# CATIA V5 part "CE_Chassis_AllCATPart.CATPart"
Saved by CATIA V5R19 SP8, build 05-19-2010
Part number: CE1_Chassis_AllCATPart
Bounding box of the stored display mesh (mm): x -239.06 to 490.902, y -240.361 to 577.812, z 217.448 to 1467.764
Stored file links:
  D:\Documents\1_Travail\1 - ac-limoges.fr\ac-limoges.fr\Emmanuel Maynard - STI2D_Turgot\2 -2I2D\1_SEQUENCE_ Tapis_de_course\3- Spécificités\Spé_ITEC\3-Pente\Tapis_TC520B_Pente\CE_Chassis_AllCATPart.CATPart
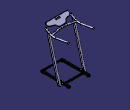
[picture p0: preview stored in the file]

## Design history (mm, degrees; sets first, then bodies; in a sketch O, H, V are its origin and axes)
AxisSystem1: origin (125.9211, -227.6434, 238.4484), X (1, 0, 0), Y (0, 1, 0), Z (0, 0, 1)
Set1 "S/S Cadre.1\\Cadre Chasis (1).1\\Références externes"
  DatumSurface1
Set2 "S/S Cadre.1\\Cadre Chasis (1).1\\Set géométrique.1"
  Sketch1 "Esquisse.38", origin (125.9211, -238.3614, 255.4484), H (0, 1, 0), V (0, 0, 1), geometry linked from another document
Body1 (main body)
  Point1: type OnCurve, Support edge [face of Solid2 | face of Solid2], Ratio 0.5
Body2 "S/S Cadre.1\\Cadre Chasis (1).1"
  Solid1: solid without history
  Body3 "S/S Cadre.1\\Cadre Chasis (1).1\\Traverses"
    Solid2 "Solide.1": solid without history
  Add1 "S/S Cadre.1\\Cadre Chasis (1).1\\Traverses": tool Body3
  Body4 "S/S Cadre.1\\Cadre Chasis (1).1\\renfort d'angle"
    Solid3 "Solide.1": solid without history
  Add2 "S/S Cadre.1\\Cadre Chasis (1).1\\renfort d'angle": tool Body4
  Body5 "S/S Cadre.1\\Cadre Chasis (1).1\\Ecrou_soudé H -M8"
    Solid4 "Solide.1": solid without history
  Add3 "S/S Cadre.1\\Cadre Chasis (1).1\\Ecrou_soudé H -M8": tool Body5
  Body6 "S/S Cadre.1\\Cadre Chasis (1).1\\Ecrou soudé H-M10"
    Solid5 "Solide.1": solid without history
  Add4 "S/S Cadre.1\\Cadre Chasis (1).1\\Ecrou soudé H-M10": tool Body6
  Body7 "S/S Cadre.1\\Cadre Chasis (1).1\\Chappe Vérin"
    Solid6 "Solide.1": solid without history
  Add5 "S/S Cadre.1\\Cadre Chasis (1).1\\Chappe Vérin": tool Body7
Body8 "S/S Cadre.1\\Patin (54).2"
  Solid7 "Solide.1": solid without history
  Body9 "S/S Cadre.1\\Patin (54).2\\Vis"
    Solid8 "Solide.1": solid without history
  Add6 "S/S Cadre.1\\Patin (54).2\\Vis": tool Body9
Body10 "S/S Cadre.1\\Patin (54).1"
  Solid9 "Solide.1": solid without history
  Body11 "S/S Cadre.1\\Patin (54).1\\Vis"
    Solid10 "Solide.1": solid without history
  Add7 "S/S Cadre.1\\Patin (54).1\\Vis": tool Body11
Body12 "S/S Cadre.1\\Patin (54).3"
  Solid11 "Solide.1": solid without history
  Body13 "S/S Cadre.1\\Patin (54).3\\Vis"
    Solid12 "Solide.1": solid without history
  Add8 "S/S Cadre.1\\Patin (54).3\\Vis": tool Body13
Body14 "S/S Cadre.1\\Patin (54).4"
  Solid13 "Solide.1": solid without history
  Body15 "S/S Cadre.1\\Patin (54).4\\Vis"
    Solid14 "Solide.1": solid without history
  Add9 "S/S Cadre.1\\Patin (54).4\\Vis": tool Body15
Body16 "S/S Cadre.1\\Part1.9\\Corps principal"
  Solid15 "Solide.1": solid without history
Body17 "S/S Cadre.1\\Part1.2\\Corps principal"
  Solid16 "Solide.1": solid without history
Body18 "S/S Cadre.1\\Vis Epaulée Tetebombee a six pan creux M10x23-9.1\\screw_gb_t_70_2_m10x25"
  Solid17 "Solide.1": solid without history
Body19 "S/S Cadre.1\\Rondelle plastique M12.1\\Corps principal"
  Solid18 "Solide.1": solid without history
Body20 "S/S Cadre.1\\Vis Epaulée Tetebombee a six pan creux M10x23-9.2\\screw_gb_t_70_2_m10x25"
  Solid19 "Solide.1": solid without history
Body21 "S/S Cadre.1\\Rondelle plastique M12.10\\Corps principal"
  Solid20 "Solide.1": solid without history
Body22 "S/S Roulette_Transport.1\\Part1.6\\Corps principal"
  Solid21 "Solide.1": solid without history
Body23 "S/S Roulette_Transport.1\\Part1.1\\Corps principal"
  Solid22 "Solide.1": solid without history
Body24 "S/S Roulette_Transport.1\\Vis ISO 7380 Tete bombee a six pans creux M8x55.1"
  Solid23 "Solide.1": solid without history
  Body25 "S/S Roulette_Transport.1\\Vis ISO 7380 Tete bombee a six pans creux M8x55.1\\Corps de pièce.2"
    Solid24 "Solide.1": solid without history
  Add10 "S/S Roulette_Transport.1\\Vis ISO 7380 Tete bombee a six pans creux M8x55.1\\Corps de pièce.2": tool Body25
Body26 "S/S Roulette_Transport.1\\Vis ISO 7380 Tete bombee a six pans creux M8x55.2"
  Solid25 "Solide.1": solid without history
  Body27 "S/S Roulette_Transport.1\\Vis ISO 7380 Tete bombee a six pans creux M8x55.2\\Corps de pièce.2"
    Solid26 "Solide.1": solid without history
  Add11 "S/S Roulette_Transport.1\\Vis ISO 7380 Tete bombee a six pans creux M8x55.2\\Corps de pièce.2": tool Body27
Body28 "S/S Roulette_Transport.1\\ecrou_iso_7040-M8-10.1\\ecrou_iso_7040-m8-10"
  Solid27 "Solide.1": solid without history
Body29 "S/S Roulette_Transport.1\\ecrou_iso_7040-M8-10.2\\ecrou_iso_7040-m8-10"
  Solid28 "Solide.1": solid without history
Body30 "S/S Montants.1\\Montant_Gauche.1\\Corps principal"
  Solid29 "Solide.1": solid without history
Body31 "S/S Montants.1\\Montant_Droit.1\\Corps principal"
  Solid30 "Solide.1": solid without history
Body32 "S/S Guidon.1\\Guidon.1\\Corps principal"
  Solid31 "Solide.1": solid without history
Body33 "S/S Guidon.1\\Pupitre.1\\Corps principal"
  Solid32 "Solide.1": solid without history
